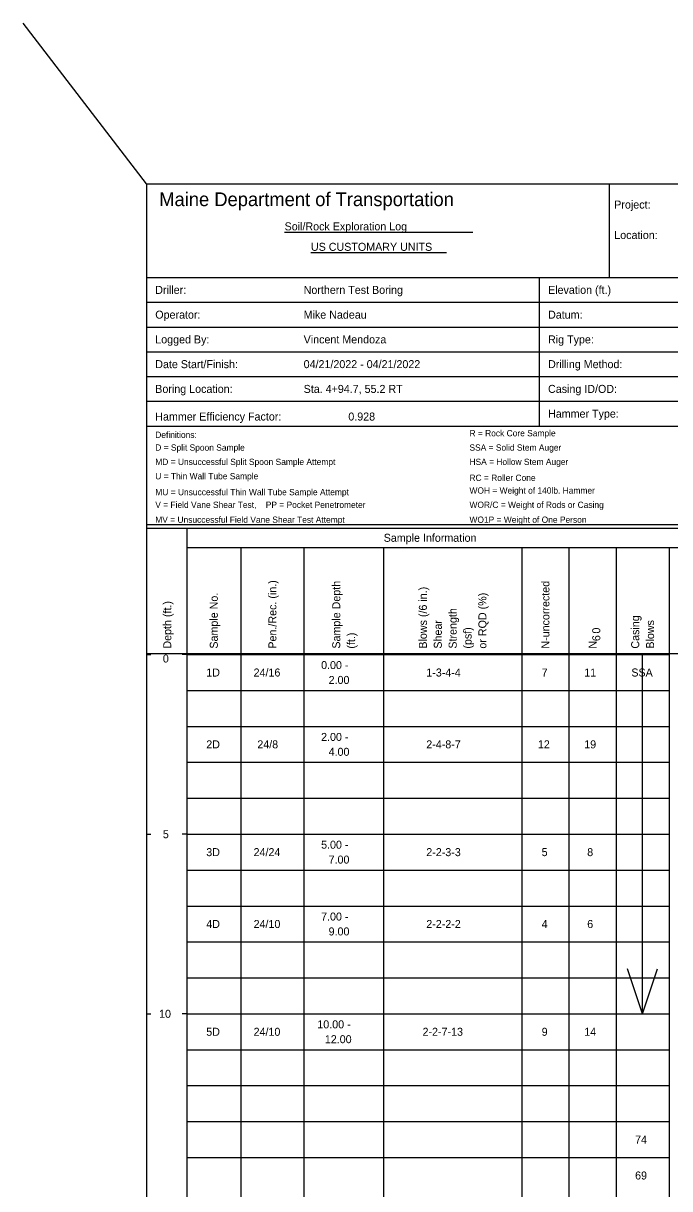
# Model space of a CAD drawing. Extents: x 9419 to 9552, y 6780 to 6865.
# Drawn here: x 9419.02 to 9437.02, y 6832.14 to 6864.58 of the extents above; entities that cross this region are included whole.
import ezdxf

# ---------------------------------------------------------------- set-up
doc = ezdxf.new("R2010")
doc.units = 0
doc.layers.add('7', color=7, linetype='Continuous')
doc.layers.add('JUNK', color=7, linetype='Continuous')

msp = doc.modelspace()

# ---------------------------------------------------------------- linework, layer by layer
at = {"layer": '7'}
for p, q in [((9426.293, 6858.771), (9431.536, 6858.771)), ((9427.027, 6858.202), (9430.802, 6858.202)), ((9436.264, 6837.011), (9436.264, 6847.011)), ((9436.264, 6837.011), (9435.847, 6838.261)), ((9436.264, 6837.011), (9436.681, 6838.261))]:
    msp.add_line(p, q, dxfattribs=at)
for points in [[(9422.449, 6860.114), (9422.449, 6821.983)], [(9422.449, 6860.114), (9453.945, 6860.114)], [(9435.331, 6860.114), (9435.331, 6857.505)], [(9422.449, 6857.505), (9453.945, 6857.505)], [(9433.387, 6857.505), (9433.387, 6854.06)], [(9422.449, 6856.816), (9453.945, 6856.816)], [(9422.449, 6856.127), (9453.945, 6856.127)], [(9422.449, 6855.438), (9453.945, 6855.438)], [(9422.449, 6854.749), (9453.945, 6854.749)], [(9422.449, 6854.06), (9453.945, 6854.06)], [(9433.387, 6854.06), (9433.387, 6853.371)], [(9422.449, 6853.371), (9453.945, 6853.371)], [(9422.449, 6850.632), (9453.945, 6850.632)], [(9422.449, 6850.528), (9453.945, 6850.528)], [(9423.567, 6850.528), (9423.567, 6821.983)], [(9423.567, 6849.992), (9438.314, 6849.992)], [(9425.076, 6849.992), (9425.076, 6821.983)], [(9426.831, 6849.992), (9426.831, 6821.983)], [(9429.046, 6849.992), (9429.046, 6821.983)], [(9432.901, 6849.992), (9432.901, 6821.983)], [(9434.213, 6849.992), (9434.213, 6821.983)], [(9435.526, 6849.992), (9435.526, 6821.983)], [(9437.002, 6849.992), (9437.002, 6821.983)], [(9422.449, 6847.038), (9453.945, 6847.038)], [(9422.449, 6847.011), (9422.571, 6847.011)], [(9423.567, 6847.011), (9423.445, 6847.011)], [(9423.567, 6847.011), (9425.076, 6847.011)], [(9425.076, 6847.011), (9426.831, 6847.011)], [(9426.831, 6847.011), (9429.046, 6847.011)], [(9429.046, 6847.011), (9432.901, 6847.011)], [(9432.901, 6847.011), (9434.213, 6847.011)], [(9434.213, 6847.011), (9435.526, 6847.011)], [(9435.526, 6847.011), (9437.002, 6847.011)], [(9423.567, 6846.011), (9425.076, 6846.011)], [(9425.076, 6846.011), (9426.831, 6846.011)], [(9426.831, 6846.011), (9429.046, 6846.011)], [(9429.046, 6846.011), (9432.901, 6846.011)], [(9432.901, 6846.011), (9434.213, 6846.011)], [(9434.213, 6846.011), (9435.526, 6846.011)], [(9435.526, 6846.011), (9437.002, 6846.011)], [(9423.567, 6845.011), (9425.076, 6845.011)], [(9425.076, 6845.011), (9426.831, 6845.011)], [(9426.831, 6845.011), (9429.046, 6845.011)], [(9429.046, 6845.011), (9432.901, 6845.011)], [(9432.901, 6845.011), (9434.213, 6845.011)], [(9434.213, 6845.011), (9435.526, 6845.011)], [(9435.526, 6845.011), (9437.002, 6845.011)], [(9423.567, 6844.011), (9425.076, 6844.011)], [(9425.076, 6844.011), (9426.831, 6844.011)], [(9426.831, 6844.011), (9429.046, 6844.011)], [(9429.046, 6844.011), (9432.901, 6844.011)], [(9432.901, 6844.011), (9434.213, 6844.011)], [(9434.213, 6844.011), (9435.526, 6844.011)], [(9435.526, 6844.011), (9437.002, 6844.011)], [(9423.567, 6843.011), (9425.076, 6843.011)], [(9425.076, 6843.011), (9426.831, 6843.011)], [(9426.831, 6843.011), (9429.046, 6843.011)], [(9429.046, 6843.011), (9432.901, 6843.011)], [(9432.901, 6843.011), (9434.213, 6843.011)], [(9434.213, 6843.011), (9435.526, 6843.011)], [(9435.526, 6843.011), (9437.002, 6843.011)], [(9422.449, 6842.011), (9422.571, 6842.011)], [(9423.567, 6842.011), (9423.445, 6842.011)], [(9423.567, 6842.011), (9425.076, 6842.011)], [(9425.076, 6842.011), (9426.831, 6842.011)], [(9426.831, 6842.011), (9429.046, 6842.011)], [(9429.046, 6842.011), (9432.901, 6842.011)], [(9432.901, 6842.011), (9434.213, 6842.011)], [(9434.213, 6842.011), (9435.526, 6842.011)], [(9435.526, 6842.011), (9437.002, 6842.011)], [(9423.567, 6841.011), (9425.076, 6841.011)], [(9425.076, 6841.011), (9426.831, 6841.011)], [(9426.831, 6841.011), (9429.046, 6841.011)], [(9429.046, 6841.011), (9432.901, 6841.011)], [(9432.901, 6841.011), (9434.213, 6841.011)], [(9434.213, 6841.011), (9435.526, 6841.011)], [(9435.526, 6841.011), (9437.002, 6841.011)], [(9423.567, 6840.011), (9425.076, 6840.011)], [(9425.076, 6840.011), (9426.831, 6840.011)], [(9426.831, 6840.011), (9429.046, 6840.011)], [(9429.046, 6840.011), (9432.901, 6840.011)], [(9432.901, 6840.011), (9434.213, 6840.011)], [(9434.213, 6840.011), (9435.526, 6840.011)], [(9435.526, 6840.011), (9437.002, 6840.011)], [(9423.567, 6839.011), (9425.076, 6839.011)], [(9425.076, 6839.011), (9426.831, 6839.011)], [(9426.831, 6839.011), (9429.046, 6839.011)], [(9429.046, 6839.011), (9432.901, 6839.011)], [(9432.901, 6839.011), (9434.213, 6839.011)], [(9434.213, 6839.011), (9435.526, 6839.011)], [(9435.526, 6839.011), (9437.002, 6839.011)], [(9423.567, 6838.011), (9425.076, 6838.011)], [(9425.076, 6838.011), (9426.831, 6838.011)], [(9426.831, 6838.011), (9429.046, 6838.011)], [(9429.046, 6838.011), (9432.901, 6838.011)], [(9432.901, 6838.011), (9434.213, 6838.011)], [(9434.213, 6838.011), (9435.526, 6838.011)], [(9435.526, 6838.011), (9437.002, 6838.011)], [(9422.449, 6837.011), (9422.571, 6837.011)], [(9423.567, 6837.011), (9423.445, 6837.011)], [(9423.567, 6837.011), (9425.076, 6837.011)], [(9425.076, 6837.011), (9426.831, 6837.011)], [(9426.831, 6837.011), (9429.046, 6837.011)], [(9429.046, 6837.011), (9432.901, 6837.011)], [(9432.901, 6837.011), (9434.213, 6837.011)], [(9434.213, 6837.011), (9435.526, 6837.011)], [(9435.526, 6837.011), (9437.002, 6837.011)], [(9423.567, 6836.011), (9425.076, 6836.011)], [(9425.076, 6836.011), (9426.831, 6836.011)], [(9426.831, 6836.011), (9429.046, 6836.011)], [(9429.046, 6836.011), (9432.901, 6836.011)], [(9432.901, 6836.011), (9434.213, 6836.011)], [(9434.213, 6836.011), (9435.526, 6836.011)], [(9435.526, 6836.011), (9437.002, 6836.011)], [(9423.567, 6835.011), (9425.076, 6835.011)], [(9425.076, 6835.011), (9426.831, 6835.011)], [(9426.831, 6835.011), (9429.046, 6835.011)], [(9429.046, 6835.011), (9432.901, 6835.011)], [(9432.901, 6835.011), (9434.213, 6835.011)], [(9434.213, 6835.011), (9435.526, 6835.011)], [(9435.526, 6835.011), (9437.002, 6835.011)], [(9423.567, 6834.011), (9425.076, 6834.011)], [(9425.076, 6834.011), (9426.831, 6834.011)], [(9426.831, 6834.011), (9429.046, 6834.011)], [(9429.046, 6834.011), (9432.901, 6834.011)], [(9432.901, 6834.011), (9434.213, 6834.011)], [(9434.213, 6834.011), (9435.526, 6834.011)], [(9435.526, 6834.011), (9437.002, 6834.011)], [(9423.567, 6833.011), (9425.076, 6833.011)], [(9425.076, 6833.011), (9426.831, 6833.011)], [(9426.831, 6833.011), (9429.046, 6833.011)], [(9429.046, 6833.011), (9432.901, 6833.011)], [(9432.901, 6833.011), (9434.213, 6833.011)], [(9434.213, 6833.011), (9435.526, 6833.011)], [(9435.526, 6833.011), (9437.002, 6833.011)]]:
    msp.add_lwpolyline(points, dxfattribs=at)
at = {"layer": 'JUNK'}
msp.add_line((9422.449, 6860.114), (9419.017, 6864.581), dxfattribs=at)

# ---------------------------------------------------------------- texts
at = {"layer": '7'}
for s, height, p in [('Maine Department of Transportation', 0.38194, (9422.803, 6859.492)), ('Project:', 0.2228, (9435.474, 6859.424)), ('Soil/Rock Exploration Log', 0.2228, (9426.293, 6858.817)), ('Location:', 0.2228, (9435.474, 6858.576)), ('US CUSTOMARY UNITS', 0.2228, (9427.027, 6858.248)), ('Driller:', 0.2228, (9422.692, 6857.049)), ('Northern Test Boring', 0.2228, (9426.824, 6857.049)), ('Elevation (ft.)', 0.2228, (9433.63, 6857.049)), ('Operator:', 0.2228, (9422.692, 6856.36)), ('Mike Nadeau', 0.2228, (9426.824, 6856.36)), ('Datum:', 0.2228, (9433.63, 6856.36)), ('Logged By:', 0.2228, (9422.692, 6855.671)), ('Vincent Mendoza', 0.2228, (9426.824, 6855.671)), ('Rig Type:', 0.2228, (9433.63, 6855.671)), ('Date Start/Finish:', 0.2228, (9422.692, 6854.982)), ('04/21/2022 - 04/21/2022', 0.2228, (9426.824, 6854.982)), ('Drilling Method:', 0.2228, (9433.63, 6854.982)), ('Boring Location:', 0.2228, (9422.692, 6854.293)), ('Sta. 4+94.7, 55.2 RT', 0.2228, (9426.824, 6854.293)), ('Casing ID/OD:', 0.2228, (9433.63, 6854.293)), ('Hammer Efficiency Factor:', 0.2228, (9422.692, 6853.524)), ('0.928', 0.2228, (9428.068, 6853.524)), ('Hammer Type:', 0.2228, (9433.63, 6853.604)), ('R = Rock Core Sample', 0.17506, (9431.442, 6853.084)), ('Definitions:', 0.17506, (9422.692, 6853.039)), ('D = Split Spoon Sample', 0.17506, (9422.692, 6852.685)), ('SSA = Solid Stem Auger', 0.17506, (9431.442, 6852.685)), ('MD = Unsuccessful Split Spoon Sample Attempt', 0.17506, (9422.692, 6852.287)), ('HSA = Hollow Stem Auger', 0.17506, (9431.442, 6852.287)), ('U = Thin Wall Tube Sample', 0.17506, (9422.692, 6851.888)), ('RC = Roller Cone', 0.17506, (9431.442, 6851.843)), ('WOH = Weight of 140lb. Hammer', 0.17506, (9431.442, 6851.489)), ('MU = Unsuccessful Thin Wall Tube Sample Attempt', 0.17506, (9422.692, 6851.444)), ('V = Field Vane Shear Test,    PP = Pocket Penetrometer', 0.17506, (9422.692, 6851.091)), ('WOR/C = Weight of Rods or Casing', 0.17506, (9431.442, 6851.091)), ('MV = Unsuccessful Field Vane Shear Test Attempt', 0.17506, (9422.692, 6850.677)), ('WO1P = Weight of One Person', 0.17506, (9431.442, 6850.677)), ('Sample Information', 0.2228, (9429.053, 6850.149)), ('0', 0.223, (9422.903, 6846.788)), ('0.00 -', 0.2228, (9427.31, 6846.606)), ('1D', 0.2228, (9424.112, 6846.399)), ('24/16', 0.2228, (9425.43, 6846.399)), ('1-3-4-4', 0.2228, (9430.239, 6846.399)), ('7', 0.223, (9433.452, 6846.399)), (' 11', 0.2228, (9434.555, 6846.399)), ('SSA', 0.2228, (9435.949, 6846.399)), ('2.00', 0.2228, (9427.519, 6846.192)), ('2.00 -', 0.2228, (9427.31, 6844.606)), ('2D', 0.2228, (9424.112, 6844.399)), ('24/8', 0.2228, (9425.534, 6844.399)), ('2-4-8-7', 0.2228, (9430.239, 6844.399)), ('12', 0.2228, (9433.347, 6844.399)), (' 19', 0.2228, (9434.555, 6844.399)), ('4.00', 0.2228, (9427.519, 6844.192)), ('5', 0.223, (9422.903, 6841.899)), ('3D', 0.2228, (9424.112, 6841.399)), ('24/24', 0.2228, (9425.43, 6841.399)), ('5.00 -', 0.2228, (9427.31, 6841.606)), ('2-2-3-3', 0.2228, (9430.239, 6841.399)), ('5', 0.223, (9433.452, 6841.399)), ('  8', 0.2228, (9434.555, 6841.399)), ('7.00', 0.2228, (9427.519, 6841.192)), ('24/10', 0.2228, (9425.43, 6839.399)), ('7.00 -', 0.2228, (9427.31, 6839.606)), ('4D', 0.2228, (9424.112, 6839.399)), ('9.00', 0.2228, (9427.519, 6839.192)), ('2-2-2-2', 0.2228, (9430.239, 6839.399)), ('4', 0.223, (9433.452, 6839.399)), ('  6', 0.2228, (9434.555, 6839.399)), ('10', 0.2228, (9422.798, 6836.899)), ('10.00 -', 0.2228, (9427.205, 6836.606)), ('5D', 0.2228, (9424.112, 6836.399)), ('24/10', 0.2228, (9425.43, 6836.399)), ('12.00', 0.2228, (9427.414, 6836.192)), ('2-2-7-13', 0.2228, (9430.135, 6836.399)), ('9', 0.223, (9433.452, 6836.399)), (' 14', 0.2228, (9434.555, 6836.399)), ('74', 0.2228, (9436.054, 6833.399)), ('69', 0.2228, (9436.054, 6832.399))]:
    msp.add_text(s, height=height, dxfattribs=at).set_placement(p)
for s, height, p in [('Pen./Rec. (in.)', 0.2228, (9426.065, 6847.175)), ('Sample Depth', 0.2228, (9427.843, 6847.175)), ('N-uncorrected', 0.2228, (9433.668, 6847.175)), ('Blows (/6 in.)', 0.2228, (9430.256, 6847.175)), ('or RQD (%%%)', 0.2228, (9431.913, 6847.175)), ('Depth (ft.)', 0.2228, (9423.137, 6847.175)), ('Sample No.', 0.2228, (9424.433, 6847.175)), ('Strength', 0.2228, (9431.085, 6847.175)), ('Casing ', 0.2228, (9436.168, 6847.175)), ('Shear', 0.2228, (9430.671, 6847.175)), ('(psf)', 0.2228, (9431.499, 6847.175)), ('0', 0.223, (9435.084, 6847.594)), ('Blows', 0.2228, (9436.582, 6847.175)), ('(ft.)', 0.2228, (9428.257, 6847.175)), ('6', 0.223, (9435.084, 6847.384)), ('N', 0.223, (9434.981, 6847.175))]:
    msp.add_text(s, height=height, rotation=90, dxfattribs=at).set_placement(p)

doc.saveas('drawing.dxf')
